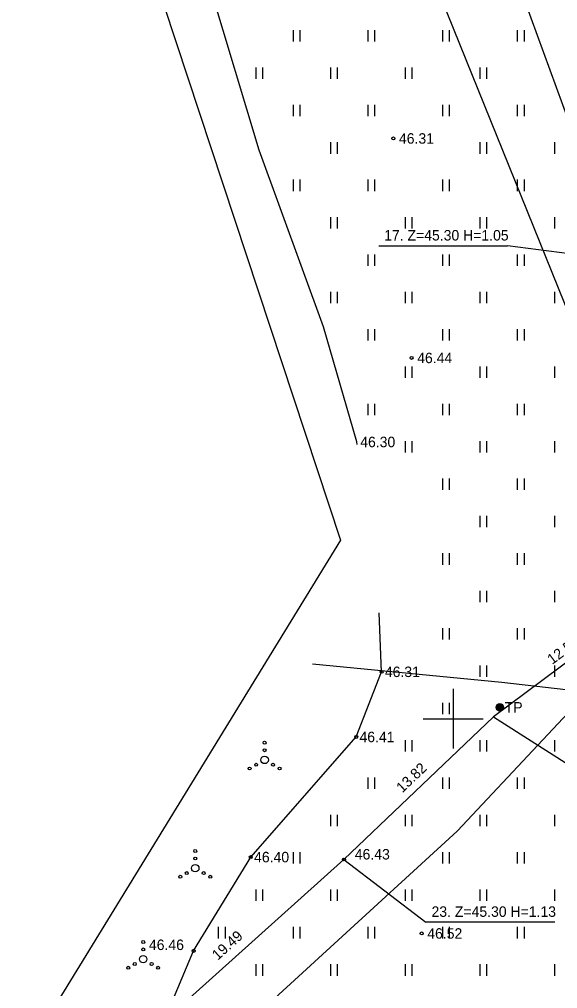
# Model space of a CAD drawing. Extents: x 642747 to 644424, y 6457048 to 6458238.
# Drawn here: x 644071 to 644107, y 6457581.9 to 6457646.8 of the extents above; entities that cross this region are included whole.
import ezdxf

# ---------------------------------------------------------------- set-up
doc = ezdxf.new("R2010")
doc.units = 0
for name, color, linetype in [('HALJASTUS', 7, 'Continuous'), ('JOONSIDE', 7, 'Continuous'), ('KOORDPUNKT', 7, 'Continuous'), ('KORGUS', 7, 'Continuous'), ('KPKAABEL', 7, 'Continuous'), ('KPOHULIIN', 7, 'Continuous'), ('MOOTPIIR', 7, 'Continuous'), ('POST', 7, 'Continuous'), ('SITRASS', 7, 'Continuous'), ('TEE', 7, 'Continuous'), ('VORK', 7, 'Continuous')]:
    doc.layers.add(name, color=color, linetype=linetype)

msp = doc.modelspace()

# ---------------------------------------------------------------- linework, layer by layer
at = {"layer": 'HALJASTUS'}
for p, q in [((644089.29, 6457646.069), (644089.29, 6457645.307)), ((644089.745, 6457646.069), (644089.745, 6457645.307)), ((644094.29, 6457646.069), (644094.29, 6457645.307)), ((644094.745, 6457646.069), (644094.745, 6457645.307)), ((644099.29, 6457646.069), (644099.29, 6457645.307)), ((644099.745, 6457646.069), (644099.745, 6457645.307)), ((644104.29, 6457646.069), (644104.29, 6457645.307)), ((644104.745, 6457646.069), (644104.745, 6457645.307)), ((644086.79, 6457643.569), (644086.79, 6457642.807)), ((644087.245, 6457643.569), (644087.245, 6457642.807)), ((644091.79, 6457643.569), (644091.79, 6457642.807)), ((644092.245, 6457643.569), (644092.245, 6457642.807)), ((644096.79, 6457643.569), (644096.79, 6457642.807)), ((644097.245, 6457643.569), (644097.245, 6457642.807)), ((644101.79, 6457643.569), (644101.79, 6457642.807)), ((644102.245, 6457643.569), (644102.245, 6457642.807)), ((644089.29, 6457641.069), (644089.29, 6457640.307)), ((644089.745, 6457641.069), (644089.745, 6457640.307)), ((644094.29, 6457641.069), (644094.29, 6457640.307)), ((644094.745, 6457641.069), (644094.745, 6457640.307)), ((644099.29, 6457641.069), (644099.29, 6457640.307)), ((644099.745, 6457641.069), (644099.745, 6457640.307)), ((644104.29, 6457641.069), (644104.29, 6457640.307)), ((644104.745, 6457641.069), (644104.745, 6457640.307)), ((644091.79, 6457638.569), (644091.79, 6457637.807)), ((644092.245, 6457638.569), (644092.245, 6457637.807)), ((644101.79, 6457638.569), (644101.79, 6457637.807)), ((644102.245, 6457638.569), (644102.245, 6457637.807)), ((644106.79, 6457638.569), (644106.79, 6457637.807)), ((644089.29, 6457636.069), (644089.29, 6457635.307)), ((644089.745, 6457636.069), (644089.745, 6457635.307)), ((644094.29, 6457636.069), (644094.29, 6457635.307)), ((644094.745, 6457636.069), (644094.745, 6457635.307)), ((644099.29, 6457636.069), (644099.29, 6457635.307)), ((644099.745, 6457636.069), (644099.745, 6457635.307)), ((644104.29, 6457636.069), (644104.29, 6457635.307)), ((644104.745, 6457636.069), (644104.745, 6457635.307)), ((644091.79, 6457633.569), (644091.79, 6457632.807)), ((644092.245, 6457633.569), (644092.245, 6457632.807)), ((644096.79, 6457633.569), (644096.79, 6457632.807)), ((644097.245, 6457633.569), (644097.245, 6457632.807)), ((644101.79, 6457633.569), (644101.79, 6457632.807)), ((644102.245, 6457633.569), (644102.245, 6457632.807)), ((644106.79, 6457633.569), (644106.79, 6457632.807)), ((644094.29, 6457631.069), (644094.29, 6457630.307)), ((644094.745, 6457631.069), (644094.745, 6457630.307)), ((644099.29, 6457631.069), (644099.29, 6457630.307)), ((644099.745, 6457631.069), (644099.745, 6457630.307)), ((644104.29, 6457631.069), (644104.29, 6457630.307)), ((644104.745, 6457631.069), (644104.745, 6457630.307)), ((644091.79, 6457628.569), (644091.79, 6457627.807)), ((644092.245, 6457628.569), (644092.245, 6457627.807)), ((644096.79, 6457628.569), (644096.79, 6457627.807)), ((644097.245, 6457628.569), (644097.245, 6457627.807)), ((644101.79, 6457628.569), (644101.79, 6457627.807)), ((644102.245, 6457628.569), (644102.245, 6457627.807)), ((644106.79, 6457628.569), (644106.79, 6457627.807)), ((644094.29, 6457626.069), (644094.29, 6457625.307)), ((644094.745, 6457626.069), (644094.745, 6457625.307)), ((644099.29, 6457626.069), (644099.29, 6457625.307)), ((644099.745, 6457626.069), (644099.745, 6457625.307)), ((644104.29, 6457626.069), (644104.29, 6457625.307)), ((644104.745, 6457626.069), (644104.745, 6457625.307)), ((644096.79, 6457623.569), (644096.79, 6457622.807)), ((644097.245, 6457623.569), (644097.245, 6457622.807)), ((644101.79, 6457623.569), (644101.79, 6457622.807)), ((644102.245, 6457623.569), (644102.245, 6457622.807)), ((644106.79, 6457623.569), (644106.79, 6457622.807)), ((644094.29, 6457621.069), (644094.29, 6457620.307)), ((644094.745, 6457621.069), (644094.745, 6457620.307)), ((644099.29, 6457621.069), (644099.29, 6457620.307)), ((644099.745, 6457621.069), (644099.745, 6457620.307)), ((644104.29, 6457621.069), (644104.29, 6457620.307)), ((644104.745, 6457621.069), (644104.745, 6457620.307)), ((644096.79, 6457618.569), (644096.79, 6457617.807)), ((644097.245, 6457618.569), (644097.245, 6457617.807)), ((644101.79, 6457618.569), (644101.79, 6457617.807)), ((644102.245, 6457618.569), (644102.245, 6457617.807)), ((644106.79, 6457618.569), (644106.79, 6457617.807)), ((644099.29, 6457616.069), (644099.29, 6457615.307)), ((644099.745, 6457616.069), (644099.745, 6457615.307)), ((644104.29, 6457616.069), (644104.29, 6457615.307)), ((644104.745, 6457616.069), (644104.745, 6457615.307)), ((644101.79, 6457613.569), (644101.79, 6457612.807)), ((644102.245, 6457613.569), (644102.245, 6457612.807)), ((644106.79, 6457613.569), (644106.79, 6457612.807)), ((644099.29, 6457611.069), (644099.29, 6457610.307)), ((644099.745, 6457611.069), (644099.745, 6457610.307)), ((644104.29, 6457611.069), (644104.29, 6457610.307)), ((644104.745, 6457611.069), (644104.745, 6457610.307)), ((644101.79, 6457608.569), (644101.79, 6457607.807)), ((644102.245, 6457608.569), (644102.245, 6457607.807)), ((644106.79, 6457608.569), (644106.79, 6457607.807)), ((644099.29, 6457606.069), (644099.29, 6457605.307)), ((644099.745, 6457606.069), (644099.745, 6457605.307)), ((644104.29, 6457606.069), (644104.29, 6457605.307)), ((644104.745, 6457606.069), (644104.745, 6457605.307)), ((644101.79, 6457603.569), (644101.79, 6457602.807)), ((644102.245, 6457603.569), (644102.245, 6457602.807)), ((644106.79, 6457603.569), (644106.79, 6457602.807)), ((644099.29, 6457601.069), (644099.29, 6457600.307)), ((644099.745, 6457601.069), (644099.745, 6457600.307)), ((644096.79, 6457598.569), (644096.79, 6457597.807)), ((644097.245, 6457598.569), (644097.245, 6457597.807)), ((644101.79, 6457598.569), (644101.79, 6457597.807)), ((644102.245, 6457598.569), (644102.245, 6457597.807)), ((644106.79, 6457598.569), (644106.79, 6457597.807)), ((644094.29, 6457596.069), (644094.29, 6457595.307)), ((644094.745, 6457596.069), (644094.745, 6457595.307)), ((644099.29, 6457596.069), (644099.29, 6457595.307)), ((644099.745, 6457596.069), (644099.745, 6457595.307)), ((644104.29, 6457596.069), (644104.29, 6457595.307)), ((644104.745, 6457596.069), (644104.745, 6457595.307)), ((644091.79, 6457593.569), (644091.79, 6457592.807)), ((644092.245, 6457593.569), (644092.245, 6457592.807)), ((644096.79, 6457593.569), (644096.79, 6457592.807)), ((644097.245, 6457593.569), (644097.245, 6457592.807)), ((644101.79, 6457593.569), (644101.79, 6457592.807)), ((644102.245, 6457593.569), (644102.245, 6457592.807)), ((644106.79, 6457593.569), (644106.79, 6457592.807)), ((644089.29, 6457591.069), (644089.29, 6457590.307)), ((644089.745, 6457591.069), (644089.745, 6457590.307)), ((644099.29, 6457591.069), (644099.29, 6457590.307)), ((644099.745, 6457591.069), (644099.745, 6457590.307)), ((644104.29, 6457591.069), (644104.29, 6457590.307)), ((644104.745, 6457591.069), (644104.745, 6457590.307)), ((644086.79, 6457588.569), (644086.79, 6457587.807)), ((644087.245, 6457588.569), (644087.245, 6457587.807)), ((644091.79, 6457588.569), (644091.79, 6457587.807)), ((644092.245, 6457588.569), (644092.245, 6457587.807)), ((644096.79, 6457588.569), (644096.79, 6457587.807)), ((644097.245, 6457588.569), (644097.245, 6457587.807)), ((644101.79, 6457588.569), (644101.79, 6457587.807)), ((644102.245, 6457588.569), (644102.245, 6457587.807)), ((644106.79, 6457588.569), (644106.79, 6457587.807)), ((644084.29, 6457586.069), (644084.29, 6457585.307)), ((644084.745, 6457586.069), (644084.745, 6457585.307)), ((644089.29, 6457586.069), (644089.29, 6457585.307)), ((644089.745, 6457586.069), (644089.745, 6457585.307)), ((644094.29, 6457586.069), (644094.29, 6457585.307)), ((644094.745, 6457586.069), (644094.745, 6457585.307)), ((644099.29, 6457586.069), (644099.29, 6457585.307)), ((644099.745, 6457586.069), (644099.745, 6457585.307)), ((644104.29, 6457586.069), (644104.29, 6457585.307)), ((644104.745, 6457586.069), (644104.745, 6457585.307)), ((644086.79, 6457583.569), (644086.79, 6457582.807)), ((644087.245, 6457583.569), (644087.245, 6457582.807)), ((644091.79, 6457583.569), (644091.79, 6457582.807)), ((644092.245, 6457583.569), (644092.245, 6457582.807)), ((644096.79, 6457583.569), (644096.79, 6457582.807)), ((644097.245, 6457583.569), (644097.245, 6457582.807)), ((644101.79, 6457583.569), (644101.79, 6457582.807)), ((644102.245, 6457583.569), (644102.245, 6457582.807)), ((644106.79, 6457583.569), (644106.79, 6457582.807))]:
    msp.add_line(p, q, dxfattribs=at)
for points in [[(644093.59, 6457618.355), (644093.565, 6457618.519), (644091.325, 6457626.212), (644087.019, 6457638.046), (644083.789, 6457648.804), (644083.837, 6457652.374), (644084.977, 6457653.397), (644088.66, 6457654.814), (644091.405, 6457655.119), (644095.028, 6457655.197), (644097.913, 6457656.324), (644101.344, 6457659.091), (644102.065, 6457659.686), (644104.362, 6457660.778)], [(644041.809, 6457571.148), (644051.359, 6457564.407), (644056.959, 6457566.734), (644063.59, 6457569.91), (644069.17, 6457572.488), (644076.19, 6457575.794), (644080.356, 6457579.056), (644082.641, 6457584.464), (644086.464, 6457590.743), (644093.515, 6457598.78), (644095.215, 6457603.14), (644095.047, 6457607.095)]]:
    msp.add_lwpolyline(points, dxfattribs=at)
for centre, radius in [((644087.388, 6457598.396), 0.1), ((644087.388, 6457597.896), 0.1), ((644087.388, 6457597.246), 0.25), ((644086.388, 6457596.671), 0.1), ((644086.823, 6457596.921), 0.1), ((644087.953, 6457596.921), 0.1), ((644088.388, 6457596.671), 0.1), ((644082.747, 6457591.149), 0.1), ((644082.747, 6457590.649), 0.1), ((644082.747, 6457589.999), 0.25), ((644081.747, 6457589.424), 0.1), ((644082.182, 6457589.674), 0.1), ((644083.312, 6457589.674), 0.1), ((644083.747, 6457589.424), 0.1), ((644079.266, 6457585.062), 0.1), ((644079.266, 6457583.912), 0.25), ((644079.266, 6457584.562), 0.1), ((644078.701, 6457583.587), 0.1), ((644079.831, 6457583.587), 0.1), ((644078.266, 6457583.337), 0.1), ((644080.266, 6457583.337), 0.1)]:
    msp.add_circle(centre, radius, dxfattribs=at)
at = {"layer": 'KOORDPUNKT'}
for p, q in [((644095.038, 6457631.648), (644103.648, 6457631.648)), ((644111.131, 6457630.665), (644103.648, 6457631.648)), ((644102.693, 6457600.124), (644108.602, 6457596.351)), ((644092.698, 6457590.582), (644098.172, 6457586.395)), ((644106.816, 6457586.395), (644098.172, 6457586.395))]:
    msp.add_line(p, q, dxfattribs=at)
for points in [[(644102.693, 6457600.124), (644102.693, 6457600.124), (644102.693, 6457600.124)], [(644092.698, 6457590.582), (644092.698, 6457590.582), (644092.698, 6457590.582)]]:
    msp.add_lwpolyline(points, dxfattribs=at)
at = {"layer": 'KORGUS'}
for centre in [(644096.002, 6457638.826), (644097.223, 6457624.142), (644095.215, 6457603.14), (644093.515, 6457598.78), (644086.464, 6457590.743), (644092.698, 6457590.582), (644097.897, 6457585.634), (644082.641, 6457584.464)]:
    msp.add_circle(centre, 0.1, dxfattribs=at)
at = {"layer": 'KPKAABEL'}
msp.add_lwpolyline([(644103.079, 6457652.715), (644111.131, 6457630.665), (644117.872, 6457612.305), (644117.831, 6457611.89), (644117.527, 6457611.592), (644112.751, 6457607.616), (644102.693, 6457600.124), (644092.698, 6457590.582), (644078.192, 6457577.561), (644066.524, 6457567.369), (644056.896, 6457559.139), (644048.865, 6457552.537), (644048.039, 6457551.927), (644047.155, 6457551.979), (644039.639, 6457557.844), (644029.553, 6457566.384), (644016.901, 6457577.396), (644002.145, 6457590.823), (643989.718, 6457602.415), (643976.894, 6457615.305), (643965.556, 6457626.702)], dxfattribs=at)
at = {"layer": 'KPOHULIIN'}
msp.add_lwpolyline([(644061.981, 6457739.913), (644094.239, 6457660.452), (644124.342, 6457586.031), (644125.691, 6457582.672)], dxfattribs=at)
at = {"layer": 'MOOTPIIR'}
msp.add_lwpolyline([(643525.446, 6457467.559), (643537.447, 6457435.458), (643944.848, 6457628.51), (644046.626, 6457529.09), (644067.022, 6457529.09), (644138.408, 6457598.401), (644075.1, 6457775.215), (644046.02, 6457752.582), (644092.466, 6457611.94), (644070.657, 6457576.375), (644041.981, 6457570.717), (643942.223, 6457662.862)], close=True, dxfattribs=at)
at = {"layer": 'POST'}
for radius in [0.25, 0.225, 0.2, 0.175, 0.15, 0.125, 0.1, 0.075, 0.05, 0.025]:
    msp.add_circle((644103.129, 6457600.766), radius, dxfattribs=at)
at = {"layer": 'SITRASS'}
msp.add_lwpolyline([(644131.692, 6457599.165), (644103.261, 6457602.416), (644090.598, 6457603.655)], dxfattribs=at)
at = {"layer": 'TEE'}
msp.add_lwpolyline([(644051.619, 6457549.694), (644075.076, 6457569.399), (644100.273, 6457592.468), (644111.741, 6457604.69), (644121.185, 6457609.883)], dxfattribs=at)
at = {"layer": 'VORK'}
for p, q in [((644100, 6457602), (644100, 6457598)), ((644098, 6457600), (644102, 6457600))]:
    msp.add_line(p, q, dxfattribs=at)

# ---------------------------------------------------------------- texts
at = {"layer": 'JOONSIDE'}
for s, rotation, p in [('12.54', 36.68168, (644106.629, 6457603.598)), ('13.82', 43.67173, (644096.6, 6457595.002)), ('19.49', 41.91206, (644084.248, 6457583.803))]:
    msp.add_text(s, height=0.7, rotation=rotation, dxfattribs=at).set_placement(p)
at = {"layer": 'KOORDPUNKT'}
for s, p in [('17. Z=45.30 H=1.05', (644095.388, 6457631.998)), ('23. Z=45.30 H=1.13', (644098.557, 6457586.745))]:
    msp.add_text(s, height=0.7, dxfattribs=at).set_placement(p)
at = {"layer": 'KORGUS'}
for s, p in [('46.31', (644096.377, 6457638.476)), ('46.44', (644097.598, 6457623.792)), ('46.30', (644093.786, 6457618.169)), ('46.31', (644095.436, 6457602.79)), ('46.41', (644093.736, 6457598.43)), ('46.43', (644093.423, 6457590.582)), ('46.40', (644086.685, 6457590.393)), ('46.52', (644098.272, 6457585.284)), ('46.46', (644079.65, 6457584.525))]:
    msp.add_text(s, height=0.7, dxfattribs=at).set_placement(p)
at = {"layer": 'POST'}
msp.add_text('TP', height=0.7, dxfattribs=at).set_placement((644103.455, 6457600.413))

doc.saveas('drawing.dxf')
